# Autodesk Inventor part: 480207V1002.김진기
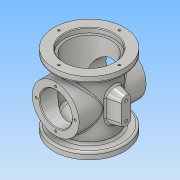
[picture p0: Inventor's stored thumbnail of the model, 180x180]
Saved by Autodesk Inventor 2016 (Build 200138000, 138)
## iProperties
Created: 2018-02
Part Number: 480207V1002.김진기
Material: 알루미늄 6061
Document SubType Name: Modeling
Designer: Administrator
Density: 2.7 g/cm^3
Appearance: 알루미늄 - 평지
Mass: 768.982 g
Surface Area: 820.894 cm^2
Volume: 284.808 cm^3
Author: Administrator
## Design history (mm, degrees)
sketch "스케치1"
  geometry: L1 (0, -54)-(0, 54); L2 (0, -54)-(-52.5, -54); L3 (-52.5, -54)-(-52.5, -44); L4 (-52.5, -44)-(-38, -44); L5 (-38, -44)-(-38, 44); L6 (-38, 44)-(-52.5, 44); L7 (-52.5, 44)-(-52.5, 54); L8 (-52.5, 54)-(0, 54); 2 further points
  constraints: 16 end point, 4 perpendicular, 2 point on line, 1 coincident, 1 horizontal, 1 midpoint, 1 parallel, 1 vertical, 1 vertical alignment
  dimensions: "d0" = 108 distance of L1.start L1.end; "d1" = 10 distance of L6.end L7.end; "d2" = 10 distance of L2.end L3.end; "d3" = 105 diameter of L7 L1; "d8" = 76 diameter of L5 L1
revolve "회전1" sketch "스케치1" stored, may be unused: angle "d5" = 90 deg
sketch "스케치3"
  geometry: L1 (-50, 0)-(50, 0); L2 (-50, 0)-(-50, 35); L3 (-50, 35)-(50, 35); L4 (50, 35)-(50, 0); 2 further points
  constraints: 8 end point, 2 perpendicular, 1 coincident, 1 horizontal, 1 midpoint, 1 vertical
  dimensions: "d9" = 100 distance of L1.start L1.end; "d10" = 70 diameter of L3 L1
revolve "회전2" sketch "스케치3" stored, may be unused: angle "d11" = 90 deg
sketch "스케치4"
  geometry: L1 (0, -32)-(0, 54); L2 (52.5, 54)-(-52.5, 54) reference; L3 (0, -32)-(-33, -32); L4 (-33, -32)-(-33, 47); L5 (-33, 47)-(-37, 47); L6 (-37, 47)-(-37, 54); L7 (-37, 54)-(0, 54); 1 further point
  constraints: 12 end point, 3 perpendicular, 2 point on line, 1 collinear, 1 horizontal, 1 midpoint, 1 vertical
  dimensions: "d22" = 74 diameter of L6 L1; "d23" = 66 diameter of L4 L1; "d24" = 7 distance between parallel lines of L2 L5; "d83" = 79 distance between parallel lines of L5 L3
revolve "회전3" sketch "스케치4" stored, may be unused: angle "d25" = 90 deg
hole "구멍2" diameter "d28" = 68; stored, may be unused: countersink angle "d32" = 90 deg, drill point angle "d34" = 0 deg; dims "d26" = 10, "d27" = 10, "d29" = 6, "d30" = 4, "d31" = 2, "d33" = 16
hole "구멍3" diameter "d37" = 10; stored, may be unused: countersink angle "d41" = 90 deg, drill point angle "d43" = 0 deg; dims "d35" = 10, "d36" = 10, "d38" = 6, "d39" = 4, "d40" = 2, "d42" = 16
hole "구멍4" diameter "d46" = 48; stored, may be unused: countersink angle "d50" = 90 deg, drill point angle "d52" = 0 deg; dims "d44" = 10, "d45" = 10, "d47" = 6, "d48" = 4, "d49" = 2, "d51" = 16
chamfer "모따기1" distance "d53" = 1; stored, may be unused: second distance "d54" = 2, angle "d55" = 45 deg
chamfer "모따기2" distance "d56" = 1; stored, may be unused: second distance "d57" = 2, angle "d58" = 45 deg
fillet "모깎기1" dims "d59" = 3
sketch "스케치5" dims "d32" = 90 deg
  geometry: 5 further points
  constraints: 2 horizontal alignment, 2 vertical alignment
  dimensions: "d60" = 45 distance of point (-45, 0) point (0, 0); "d61" = 45 distance of point (45, 0) point (0, 0); "d62" = 45 distance of point (0, 0) point (0, -45); "d63" = 45 distance of point (0, 45) point (0, 0)
hole "구멍5" sketch "스케치5" at (45, 0), (0, -45), (-45, 0), (0, 45) diameter "d64" = 3.242; stored, may be unused: countersink angle "d32" = 90 deg, countersink angle "d68" = 90 deg, drill point angle "d70" = 118 deg; dims "d65" = 4, "d66" = 4, "d67" = 2, "d69" = 6
fillet "모깎기2" dims "d71" = 3
sketch "스케치6"
  geometry: 5 further points
  constraints: 2 horizontal alignment, 2 vertical alignment
  dimensions: "d72" = 29 distance of point (-29, 0) point (0, 0); "d73" = 29 distance of point (29, 0) point (0, 0); "d74" = 29 distance of point (0, 29) point (0, 0); "d75" = 29 distance of point (0, -29) point (0, 0)
hole "구멍6" sketch "스케치6" at (0, 29), (29, 0), (0, -29), (-29, 0) diameter "d76" = 3.242; stored, may be unused: countersink angle "d80" = 90 deg, drill point angle "d82" = 118 deg; dims "d77" = 4, "d78" = 4, "d79" = 2, "d81" = 6
node "작업 평면2"
sketch "스케치7"
  geometry: L1 (-7, -13)-(-7, 13); L2 (7, -13)-(7, 13); A1 r 7 centre (0, 13) between (7, 13) and (-7, 13); A2 r 7 centre (0, -13) between (-7, -13) and (7, -13); 1 further point
  constraints: 4 end point, 4 point on circle, 3 tangent, 2 centre point, 2 vertical alignment, 1 parallel
  dimensions: "d85" = 7 radius of A1; "d86" = 7 radius of A2; "d88" = 13 distance of point (0, 0) A2.centre; "d89" = 13 distance of A1.centre point (0, 0)
extrude "돌출1" join sketch "스케치7" stored distance "d90" = 10; taper "d91" = 15 deg
fillet "모깎기3" dims "d92" = 3
hole "구멍7" diameter "d95" = 4.134; stored, may be unused: countersink angle "d99" = 90 deg, drill point angle "d101" = 118 deg; dims "d93" = 10, "d94" = 10, "d96" = 6, "d97" = 4, "d98" = 2, "d100" = 8
hole "구멍8" diameter "d104" = 4.134; stored, may be unused: countersink angle "d108" = 90 deg, drill point angle "d110" = 118 deg; dims "d102" = 10, "d103" = 10, "d105" = 6, "d106" = 4, "d107" = 2, "d109" = 8
node "솔리드1"
mirror "대칭1"
other parameters: "d84" = 55
